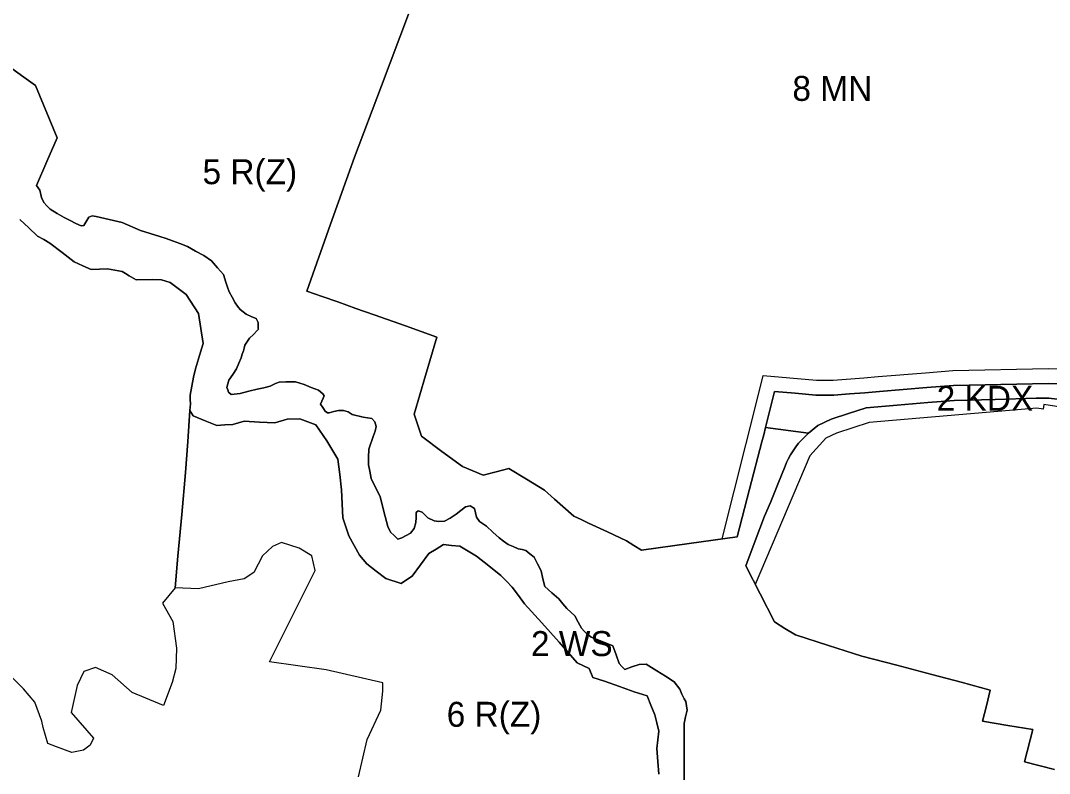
# Model space of a CAD drawing. Extents: x 7423432 to 7425824, y 5537848 to 5539677.
# Drawn here: x 7423877.3 to 7424289.1, y 5538119 to 5538420.5 of the extents above; entities that cross this region are included whole.
import ezdxf

# ---------------------------------------------------------------- set-up
doc = ezdxf.new("R2010")
doc.units = 0
for name, color, linetype in [('linie_rozgraniczajace', 7, 'Continuous'), ('linie_zabudowy_nieprzekraczalne', 7, 'Continuous'), ('oznaczenia_przeznaczen', 7, 'Continuous')]:
    doc.layers.add(name, color=color, linetype=linetype)

msp = doc.modelspace()

# ---------------------------------------------------------------- linework, layer by layer
at = {"layer": 'linie_rozgraniczajace'}
for points in [[(7423991.87, 5538312.06), (7424001.41, 5538338.89), (7424010.95, 5538365.72), (7424021.79, 5538394.37), (7424032.63, 5538423.01)], [(7424032.63, 5538423.01), (7424021.79, 5538394.37), (7424010.95, 5538365.72), (7424001.41, 5538338.89), (7423991.87, 5538312.06), (7423998.06, 5538309.91), (7424004.25, 5538307.77), (7424011.58, 5538305.17), (7424018.92, 5538302.58), (7424031.43, 5538298.16), (7424043.93, 5538293.74), (7424039.42, 5538278.32), (7424034.91, 5538262.9), (7424036.37, 5538258.45), (7424037.83, 5538254), (7424045.99, 5538247.95), (7424054.16, 5538241.89), (7424058.32, 5538240.15), (7424062.47, 5538238.41), (7424067.63, 5538239.74), (7424072.79, 5538241.07), (7424079.89, 5538236.76), (7424086.99, 5538232.44), (7424091.06, 5538228.75), (7424098.73, 5538222), (7424101.67, 5538220.62), (7424104.61, 5538219.24), (7424112.21, 5538215.69), (7424117.33, 5538213.3), (7424119.82, 5538212.14), (7424122.81, 5538210.23), (7424125.8, 5538208.32), (7424144.96, 5538211.02), (7424164.12, 5538213.72), (7424169.09, 5538232.74), (7424174.06, 5538251.75), (7424174.78, 5538254.61), (7424175.5, 5538257.47), (7424192.66, 5538255.29), (7424188.76, 5538251.27), (7424187.65, 5538249.74), (7424186.54, 5538248.2), (7424185.54, 5538246.52), (7424184.53, 5538244.85), (7424183.96, 5538243.44), (7424183.39, 5538242.04), (7424180.43, 5538234.77), (7424177.48, 5538227.5), (7424175.14, 5538221.98), (7424171.36, 5538212.06), (7424167.58, 5538202.15), (7424173.35, 5538190.89), (7424179.12, 5538179.63)], [(7423918.01, 5538339.57), (7423912.81, 5538340.81), (7423907.61, 5538342.06), (7423905.99, 5538342.25), (7423904.7, 5538341.7), (7423902.64, 5538338.35), (7423901.62, 5538338.21), (7423899.49, 5538339.2), (7423897.14, 5538340.37), (7423894.79, 5538341.54), (7423891.97, 5538343.22), (7423889.14, 5538344.9), (7423887.86, 5538346.24), (7423886.58, 5538347.58), (7423885.73, 5538349.58), (7423885.04, 5538352.54), (7423883.72, 5538354.42), (7423887.88, 5538363.99), (7423892.04, 5538373.57), (7423883.3, 5538394.46), (7423878.57, 5538397.86), (7423873.83, 5538401.26)], [(7423873.83, 5538401.26), (7423878.57, 5538397.86), (7423883.3, 5538394.46), (7423892.04, 5538373.57), (7423887.88, 5538363.99), (7423883.72, 5538354.42), (7423885.04, 5538352.54), (7423885.73, 5538349.58), (7423886.58, 5538347.58), (7423887.86, 5538346.24), (7423889.14, 5538344.9), (7423891.97, 5538343.22), (7423894.79, 5538341.54), (7423897.14, 5538340.37), (7423899.49, 5538339.2), (7423901.62, 5538338.21), (7423902.64, 5538338.35), (7423904.7, 5538341.7), (7423905.99, 5538342.25), (7423907.61, 5538342.06), (7423912.81, 5538340.81), (7423918.01, 5538339.57), (7423925.28, 5538336.37), (7423929.15, 5538335.19), (7423933.03, 5538334), (7423935.55, 5538333.16), (7423938.08, 5538332.32), (7423941.1, 5538331.16), (7423944.11, 5538330.01), (7423947.37, 5538328.18), (7423950.62, 5538326.34), (7423953.72, 5538324.24), (7423956.1, 5538321.5)], [(7423877.01, 5538340.77), (7423880.57, 5538337.47), (7423884.12, 5538334.18), (7423886.59, 5538332.76), (7423889.05, 5538331.34), (7423893.91, 5538327.59), (7423898.76, 5538323.85), (7423902.19, 5538322.29), (7423905.61, 5538320.73), (7423908.89, 5538320.86), (7423912.18, 5538321), (7423915.06, 5538320.49), (7423917.95, 5538319.99), (7423919.36, 5538319.11), (7423920.77, 5538318.23), (7423923.57, 5538316.63), (7423930.17, 5538316.75), (7423933.71, 5538316.64), (7423935.47, 5538316.09), (7423937.23, 5538315.55), (7423943.66, 5538310.74), (7423948.48, 5538303.19), (7423949.45, 5538297.19), (7423950.42, 5538291.19), (7423949.36, 5538287.71), (7423947.41, 5538280.97), (7423946.52, 5538277.7), (7423945.84, 5538274.1), (7423945.15, 5538270.5), (7423945.24, 5538268.73), (7423945.33, 5538266.96), (7423945.09, 5538264.34), (7423944.23, 5538251.91), (7423943.37, 5538239.48), (7423941.83, 5538222.72), (7423940.29, 5538205.97), (7423939.14, 5538193.23), (7423934.12, 5538187.13), (7423938.27, 5538179.8), (7423939.74, 5538169.09), (7423939.5, 5538160.93), (7423937.96, 5538155.39), (7423934.56, 5538146.18), (7423921.97, 5538151.34), (7423913.99, 5538158.45), (7423907.31, 5538161.36), (7423902.7, 5538159.77), (7423900.03, 5538154.17), (7423897.53, 5538143.3), (7423906.46, 5538133.01), (7423905.24, 5538130.27), (7423902.52, 5538128.21), (7423897.8, 5538127.29), (7423891.69, 5538129.62), (7423888.29, 5538130.9), (7423886.33, 5538137.3), (7423885.87, 5538139.83), (7423883.03, 5538147.47), (7423878.5, 5538152.86), (7423877.33, 5538153.99), (7423872.44, 5538158.9)], [(7424132.83, 5538118.67), (7424132.43, 5538123.79), (7424132.03, 5538128.9), (7424132.44, 5538132.38), (7424132.85, 5538135.87), (7424132.01, 5538139.16), (7424131.17, 5538142.44), (7424129.64, 5538146.23), (7424128.1, 5538150.01), (7424122.87, 5538151.62), (7424116.99, 5538153.79), (7424111.11, 5538155.95), (7424106.32, 5538157.38), (7424104.96, 5538160.92), (7424100.11, 5538163.28), (7424096.52, 5538167.41), (7424092.93, 5538171.54), (7424086, 5538179.23), (7424079.07, 5538186.92), (7424076.56, 5538190.26), (7424074.04, 5538193.6), (7424071.82, 5538195.89), (7424069.6, 5538198.18), (7424064.71, 5538202.09), (7424059.82, 5538206), (7424056.48, 5538207.96), (7424053.14, 5538209.92), (7424049.87, 5538210.25), (7424046.6, 5538210.58), (7424043.64, 5538208.81), (7424040.68, 5538207.04), (7424037.35, 5538202.48), (7424034.02, 5538197.92), (7424031.82, 5538196.5), (7424029.62, 5538195.08), (7424023.52, 5538197.04), (7424019.71, 5538199.98), (7424015.89, 5538202.92), (7424013.02, 5538206.31), (7424010.86, 5538210.18), (7424008.7, 5538214.05), (7424007.54, 5538217.66), (7424006.38, 5538221.26), (7424006.06, 5538226.91), (7424005.74, 5538232.55), (7424005.06, 5538238.68), (7424004.37, 5538244.8), (7423999.96, 5538252.17), (7423995.48, 5538258.5), (7423989.13, 5538260.92), (7423984.04, 5538260.87), (7423979.09, 5538259.34), (7423972.93, 5538259.69), (7423966.77, 5538260.03), (7423962.31, 5538258.75), (7423959.09, 5538258.5), (7423955.87, 5538258.25), (7423951.17, 5538260.19), (7423946.47, 5538262.12), (7423945.09, 5538264.34), (7423945.33, 5538266.96), (7423945.24, 5538268.73), (7423945.15, 5538270.5), (7423945.84, 5538274.1), (7423946.52, 5538277.7), (7423947.41, 5538280.97), (7423949.36, 5538287.71), (7423950.42, 5538291.19), (7423949.45, 5538297.19), (7423948.48, 5538303.19), (7423943.66, 5538310.74), (7423937.23, 5538315.55), (7423935.47, 5538316.09), (7423933.71, 5538316.64), (7423930.17, 5538316.75), (7423923.57, 5538316.63), (7423920.77, 5538318.23), (7423919.36, 5538319.11), (7423917.95, 5538319.99), (7423915.06, 5538320.49), (7423912.18, 5538321), (7423908.89, 5538320.86), (7423905.61, 5538320.73), (7423902.19, 5538322.29), (7423898.76, 5538323.85), (7423893.91, 5538327.59), (7423889.05, 5538331.34), (7423886.59, 5538332.76), (7423884.12, 5538334.18), (7423880.57, 5538337.47), (7423877.01, 5538340.77)], [(7424044.79, 5538219.83), (7424042.88, 5538220.17), (7424040.3, 5538221.32), (7424038.13, 5538223.55), (7424036.42, 5538224.14), (7424035.68, 5538223.39), (7424035.63, 5538221.42), (7424035.59, 5538219.46), (7424034.84, 5538217.01), (7424033.43, 5538215.13), (7424029.87, 5538213.27), (7424028.28, 5538212.74), (7424026.87, 5538214.18), (7424025.45, 5538215.61), (7424024.27, 5538217.91), (7424022.75, 5538223.89), (7424021.24, 5538229.86), (7424019.41, 5538233.44), (7424017.59, 5538237.03), (7424017.08, 5538240.03), (7424016.65, 5538242.53), (7424016.6, 5538244.03), (7424016.54, 5538245.52), (7424016.74, 5538248.87), (7424017.21, 5538250.41), (7424017.87, 5538252.3), (7424018.44, 5538253.88), (7424019.3, 5538256.08), (7424019.68, 5538257.88), (7424019.18, 5538259.8), (7424017.98, 5538261.11), (7424014.48, 5538261.63), (7424010.09, 5538262.7), (7424008.51, 5538263.71), (7424006.56, 5538264.31), (7424004.58, 5538264.35), (7424002.69, 5538263.84), (7424000.81, 5538263.33), (7424000.12, 5538263.39), (7423999.3, 5538264.09), (7423998.32, 5538265.49), (7423997.35, 5538266.88), (7423998.43, 5538269.28), (7423998.89, 5538270.15), (7423998.31, 5538271.02), (7423996.52, 5538272.39), (7423993.69, 5538273.53), (7423990.87, 5538274.66), (7423987.35, 5538275.83), (7423983.48, 5538275.85), (7423980.86, 5538275.6), (7423979.42, 5538275.13), (7423977.19, 5538274.05), (7423974.75, 5538273.37), (7423972.06, 5538272.91), (7423968.63, 5538272), (7423965.2, 5538271.1), (7423961.58, 5538270.78), (7423960.59, 5538271.69), (7423960.24, 5538272.62), (7423959.89, 5538273.55), (7423960.68, 5538276.45), (7423962.23, 5538278.74), (7423963.78, 5538281.02), (7423964.7, 5538283.23), (7423965.61, 5538285.44), (7423966.06, 5538286.83), (7423966.5, 5538288.23), (7423966.77, 5538289.33), (7423967.04, 5538290.43), (7423968.93, 5538293.24), (7423970.51, 5538294.79), (7423972.09, 5538296.35), (7423972.5, 5538296.88), (7423972.49, 5538297.17), (7423972.47, 5538298.19), (7423972.45, 5538299.51), (7423971.66, 5538301.18), (7423969.9, 5538301.85), (7423967.57, 5538302.95), (7423965.23, 5538304.81), (7423964.19, 5538306.11), (7423963.16, 5538307.4), (7423962, 5538309.63), (7423960.85, 5538311.86), (7423960.17, 5538313.76), (7423959.49, 5538315.65), (7423958.49, 5538318.75), (7423956.1, 5538321.5), (7423953.72, 5538324.24), (7423950.62, 5538326.34), (7423947.37, 5538328.18), (7423944.11, 5538330.01), (7423941.1, 5538331.16), (7423938.08, 5538332.32), (7423935.55, 5538333.16), (7423933.03, 5538334), (7423929.15, 5538335.19), (7423925.28, 5538336.37), (7423918.01, 5538339.57)], [(7423956.1, 5538321.5), (7423958.49, 5538318.75), (7423959.49, 5538315.65), (7423960.17, 5538313.76), (7423960.85, 5538311.86), (7423962, 5538309.63), (7423963.16, 5538307.4), (7423964.19, 5538306.11), (7423965.23, 5538304.81), (7423967.57, 5538302.95), (7423969.9, 5538301.85), (7423971.66, 5538301.18), (7423972.45, 5538299.51), (7423972.47, 5538298.19), (7423972.49, 5538297.17), (7423972.5, 5538296.88), (7423972.09, 5538296.35), (7423970.51, 5538294.79), (7423968.93, 5538293.24), (7423967.04, 5538290.43), (7423966.77, 5538289.33), (7423966.5, 5538288.23), (7423966.06, 5538286.83), (7423965.61, 5538285.44), (7423964.7, 5538283.23), (7423963.78, 5538281.02), (7423962.23, 5538278.74), (7423960.68, 5538276.45), (7423959.89, 5538273.55), (7423960.24, 5538272.62), (7423960.59, 5538271.69), (7423961.58, 5538270.78), (7423965.2, 5538271.1), (7423968.63, 5538272), (7423972.06, 5538272.91), (7423974.75, 5538273.37), (7423977.19, 5538274.05), (7423979.42, 5538275.13), (7423980.86, 5538275.6), (7423983.48, 5538275.85), (7423987.35, 5538275.83), (7423990.87, 5538274.66), (7423993.69, 5538273.53), (7423996.52, 5538272.39), (7423998.31, 5538271.02), (7423998.89, 5538270.15), (7423998.43, 5538269.28), (7423997.35, 5538266.88), (7423998.32, 5538265.49), (7423999.3, 5538264.09), (7424000.12, 5538263.39), (7424000.81, 5538263.33), (7424002.69, 5538263.84), (7424004.58, 5538264.35), (7424006.56, 5538264.31), (7424008.51, 5538263.71), (7424010.09, 5538262.7), (7424014.48, 5538261.63), (7424017.98, 5538261.11), (7424019.18, 5538259.8), (7424019.68, 5538257.88), (7424019.3, 5538256.08), (7424018.44, 5538253.88), (7424017.87, 5538252.3), (7424017.21, 5538250.41), (7424016.74, 5538248.87), (7424016.54, 5538245.52), (7424016.6, 5538244.03), (7424016.65, 5538242.53), (7424017.08, 5538240.03), (7424017.59, 5538237.03), (7424019.41, 5538233.44), (7424021.24, 5538229.86), (7424022.75, 5538223.89), (7424024.27, 5538217.91), (7424025.45, 5538215.61), (7424026.87, 5538214.18), (7424028.28, 5538212.74), (7424029.87, 5538213.27), (7424033.43, 5538215.13), (7424034.84, 5538217.01), (7424035.59, 5538219.46), (7424035.63, 5538221.42), (7424035.68, 5538223.39), (7424036.42, 5538224.14), (7424038.13, 5538223.55), (7424040.3, 5538221.32), (7424042.88, 5538220.17), (7424044.79, 5538219.83), (7424046.95, 5538219.92), (7424049.21, 5538221.2), (7424051.64, 5538222.84), (7424053.49, 5538224.26), (7424055.37, 5538225.69), (7424057.23, 5538226.16), (7424059.03, 5538225.04), (7424059.44, 5538223.29), (7424059.86, 5538221.53), (7424060.98, 5538219.82), (7424063.76, 5538217.94)], [(7424296.11, 5538274.99), (7424288.7, 5538275.17), (7424269.7, 5538274.72), (7424250.71, 5538274.27), (7424245.36, 5538273.87), (7424240.02, 5538273.46), (7424230.55, 5538272.68), (7424221.08, 5538271.9), (7424218.18, 5538271.65), (7424215.28, 5538271.41), (7424209.05, 5538270.94), (7424202.82, 5538270.47), (7424199.22, 5538270.49), (7424195.61, 5538270.51), (7424187.37, 5538271.2), (7424179.13, 5538271.9), (7424175.5, 5538257.47), (7424174.78, 5538254.61), (7424174.06, 5538251.75), (7424169.09, 5538232.74), (7424164.12, 5538213.72), (7424144.96, 5538211.02), (7424125.8, 5538208.32), (7424122.81, 5538210.23), (7424119.82, 5538212.14), (7424117.33, 5538213.3), (7424112.21, 5538215.69), (7424104.61, 5538219.24), (7424101.67, 5538220.62), (7424098.73, 5538222), (7424091.06, 5538228.75), (7424086.99, 5538232.44), (7424079.89, 5538236.76), (7424072.79, 5538241.07), (7424067.63, 5538239.74), (7424062.47, 5538238.41), (7424058.32, 5538240.15), (7424054.16, 5538241.89), (7424045.99, 5538247.95), (7424037.83, 5538254), (7424036.37, 5538258.45), (7424034.91, 5538262.9), (7424039.42, 5538278.32), (7424043.93, 5538293.74), (7424031.43, 5538298.16), (7424018.92, 5538302.58), (7424011.58, 5538305.17), (7424004.25, 5538307.77), (7423998.06, 5538309.91), (7423991.87, 5538312.06)], [(7424296.63, 5538268.28), (7424288.93, 5538269.22), (7424286.37, 5538269.23), (7424283.82, 5538269.23), (7424267.42, 5538268.76), (7424251.02, 5538268.28), (7424245.76, 5538267.88), (7424240.49, 5538267.47), (7424228.14, 5538266.45), (7424215.78, 5538265.43), (7424208.75, 5538263.13), (7424201.72, 5538260.84), (7424196.4, 5538258.31), (7424192.66, 5538255.29), (7424175.5, 5538257.47), (7424179.13, 5538271.9), (7424187.37, 5538271.2), (7424195.61, 5538270.51), (7424199.22, 5538270.49), (7424202.82, 5538270.47), (7424209.05, 5538270.94), (7424215.28, 5538271.41), (7424218.18, 5538271.65), (7424221.08, 5538271.9), (7424230.55, 5538272.68), (7424240.02, 5538273.46), (7424245.36, 5538273.87), (7424250.71, 5538274.27), (7424269.7, 5538274.72), (7424288.7, 5538275.17), (7424296.11, 5538274.99)], [(7424167.58, 5538202.15), (7424171.36, 5538212.06), (7424175.14, 5538221.98), (7424177.48, 5538227.5), (7424180.43, 5538234.77), (7424183.39, 5538242.04), (7424183.96, 5538243.44), (7424184.53, 5538244.85), (7424185.54, 5538246.52), (7424186.54, 5538248.2), (7424187.65, 5538249.74), (7424188.76, 5538251.27), (7424192.66, 5538255.29), (7424196.4, 5538258.31), (7424201.72, 5538260.84), (7424208.75, 5538263.13), (7424215.78, 5538265.43), (7424228.14, 5538266.45), (7424240.49, 5538267.47), (7424245.76, 5538267.88), (7424251.02, 5538268.28), (7424267.42, 5538268.76), (7424283.82, 5538269.23), (7424286.37, 5538269.23), (7424288.93, 5538269.22), (7424296.63, 5538268.28)], [(7423939.14, 5538193.23), (7423940.29, 5538205.97), (7423941.83, 5538222.72), (7423943.37, 5538239.48), (7423944.23, 5538251.91), (7423945.09, 5538264.34), (7423946.47, 5538262.12), (7423951.17, 5538260.19), (7423955.87, 5538258.25), (7423959.09, 5538258.5), (7423962.31, 5538258.75), (7423966.77, 5538260.03), (7423972.93, 5538259.69), (7423979.09, 5538259.34), (7423984.04, 5538260.87), (7423989.13, 5538260.92), (7423995.48, 5538258.5), (7423999.96, 5538252.17), (7424004.37, 5538244.8), (7424005.06, 5538238.68), (7424005.74, 5538232.55), (7424006.06, 5538226.91), (7424006.38, 5538221.26), (7424007.54, 5538217.66), (7424008.7, 5538214.05), (7424010.86, 5538210.18), (7424013.02, 5538206.31), (7424015.89, 5538202.92), (7424019.71, 5538199.98), (7424023.52, 5538197.04), (7424029.62, 5538195.08), (7424031.82, 5538196.5), (7424034.02, 5538197.92), (7424037.35, 5538202.48), (7424040.68, 5538207.04), (7424043.64, 5538208.81), (7424046.6, 5538210.58), (7424049.87, 5538210.25), (7424053.14, 5538209.92), (7424056.48, 5538207.96), (7424059.82, 5538206), (7424064.71, 5538202.09), (7424069.6, 5538198.18), (7424071.82, 5538195.89), (7424074.04, 5538193.6), (7424076.56, 5538190.26), (7424079.07, 5538186.92), (7424086, 5538179.23), (7424092.93, 5538171.54), (7424096.52, 5538167.41), (7424100.11, 5538163.28), (7424104.96, 5538160.92), (7424106.32, 5538157.38), (7424111.11, 5538155.95), (7424116.99, 5538153.79), (7424122.87, 5538151.62), (7424128.1, 5538150.01), (7424129.64, 5538146.23), (7424131.17, 5538142.44), (7424132.01, 5538139.16), (7424132.85, 5538135.87), (7424132.44, 5538132.38), (7424132.03, 5538128.9), (7424132.43, 5538123.79), (7424132.83, 5538118.67)], [(7424142.93, 5538116.41), (7424142.91, 5538127.67), (7424142.88, 5538138.93), (7424143.48, 5538141.62), (7424144.08, 5538144.31), (7424143.81, 5538146.03), (7424143.55, 5538147.76), (7424142.87, 5538148.81), (7424142.02, 5538150.75), (7424141.17, 5538152.68), (7424138.88, 5538155.68), (7424135.45, 5538157.84), (7424132.02, 5538159.99), (7424129.9, 5538161.33), (7424127.78, 5538162.66), (7424124.89, 5538162.61), (7424122, 5538161.61), (7424119.12, 5538160.61), (7424118, 5538161.79), (7424116.89, 5538162.97), (7424115.67, 5538166.49), (7424114.44, 5538170.01), (7424110.1, 5538171.75), (7424105.76, 5538173.49), (7424104.87, 5538174.14), (7424103.98, 5538174.8), (7424102.94, 5538175.95), (7424101.89, 5538177.11), (7424100.51, 5538179.6), (7424099.12, 5538182.08), (7424097.52, 5538183.54), (7424095.92, 5538184.99), (7424094.34, 5538186.91), (7424092.75, 5538188.84), (7424089.96, 5538191.33), (7424087.16, 5538193.83), (7424086.42, 5538196.95), (7424085.67, 5538200.08), (7424084.27, 5538202.83), (7424082.87, 5538205.58), (7424081.2, 5538206.94), (7424079.53, 5538208.29), (7424078.04, 5538208.59), (7424076.54, 5538208.9), (7424074.5, 5538209.8), (7424072.45, 5538210.69), (7424070.64, 5538211.98), (7424068.83, 5538213.26), (7424066.29, 5538215.6), (7424063.76, 5538217.94), (7424060.98, 5538219.82), (7424059.86, 5538221.53), (7424059.44, 5538223.29), (7424059.03, 5538225.04), (7424057.23, 5538226.16), (7424055.37, 5538225.69), (7424053.49, 5538224.26), (7424051.64, 5538222.84), (7424049.21, 5538221.2), (7424046.95, 5538219.92), (7424044.79, 5538219.83)], [(7424063.76, 5538217.94), (7424066.29, 5538215.6), (7424068.83, 5538213.26), (7424070.64, 5538211.98), (7424072.45, 5538210.69), (7424074.5, 5538209.8), (7424076.54, 5538208.9), (7424078.04, 5538208.59), (7424079.53, 5538208.29), (7424081.2, 5538206.94), (7424082.87, 5538205.58), (7424084.27, 5538202.83), (7424085.67, 5538200.08), (7424086.42, 5538196.95), (7424087.16, 5538193.83), (7424089.96, 5538191.33), (7424092.75, 5538188.84), (7424094.34, 5538186.91), (7424095.92, 5538184.99), (7424097.52, 5538183.54), (7424099.12, 5538182.08), (7424100.51, 5538179.6), (7424101.89, 5538177.11), (7424102.94, 5538175.95), (7424103.98, 5538174.8), (7424104.87, 5538174.14), (7424105.76, 5538173.49), (7424110.1, 5538171.75), (7424114.44, 5538170.01), (7424115.67, 5538166.49), (7424116.89, 5538162.97), (7424118, 5538161.79), (7424119.12, 5538160.61), (7424122, 5538161.61), (7424124.89, 5538162.61), (7424127.78, 5538162.66), (7424129.9, 5538161.33), (7424132.02, 5538159.99), (7424135.45, 5538157.84), (7424138.88, 5538155.68), (7424141.17, 5538152.68), (7424142.02, 5538150.75), (7424142.87, 5538148.81), (7424143.55, 5538147.76), (7424143.81, 5538146.03), (7424144.08, 5538144.31), (7424143.48, 5538141.62), (7424142.88, 5538138.93), (7424142.91, 5538127.67), (7424142.93, 5538116.41)], [(7424012.61, 5538117.65), (7424016.04, 5538132.48), (7424021.57, 5538144.34), (7424022.33, 5538151.91), (7424022.33, 5538155.19), (7423999.65, 5538160.4), (7423976.97, 5538163.65), (7423995.21, 5538200.25), (7423993.88, 5538206.16), (7423988.8, 5538209.2), (7423981.76, 5538211.38), (7423978.11, 5538209.89), (7423974.21, 5538206.14), (7423970.7, 5538199.43), (7423966.76, 5538196.95), (7423960.45, 5538195.66), (7423948.59, 5538192.88), (7423939.14, 5538193.23)], [(7424291.16, 5538120.58), (7424279.12, 5538123.64), (7424282.51, 5538136.57), (7424272.42, 5538138.21), (7424262.33, 5538139.85), (7424263.89, 5538146.09), (7424265.46, 5538152.33), (7424253.75, 5538155.46), (7424242.04, 5538158.58), (7424228.05, 5538162.28), (7424214.06, 5538165.97), (7424200.76, 5538170.22), (7424187.47, 5538174.47), (7424183.29, 5538177.05), (7424179.12, 5538179.63), (7424173.35, 5538190.89), (7424167.58, 5538202.15)], [(7424179.12, 5538179.63), (7424183.29, 5538177.05), (7424187.47, 5538174.47), (7424200.76, 5538170.22), (7424214.06, 5538165.97), (7424228.05, 5538162.28), (7424242.04, 5538158.58), (7424253.75, 5538155.46), (7424265.46, 5538152.33), (7424263.89, 5538146.09), (7424262.33, 5538139.85), (7424272.42, 5538138.21), (7424282.51, 5538136.57), (7424279.12, 5538123.64), (7424291.16, 5538120.58)]]:
    msp.add_lwpolyline(points, dxfattribs=at)
at = {"layer": 'linie_zabudowy_nieprzekraczalne'}
for points in [[(7424158.13, 5538212.88), (7424172.38, 5538269.69), (7424174.56, 5538278.3), (7424195.88, 5538276.5), (7424202.61, 5538276.47), (7424214.81, 5538277.39), (7424220.58, 5538277.88), (7424239.54, 5538279.44), (7424250.41, 5538280.27), (7424288.71, 5538281.18), (7424303.64, 5538280.8)], [(7424309.1, 5538263.27), (7424286.91, 5538266.75), (7424286.63, 5538264.9), (7424284.05, 5538265.29), (7424216.97, 5538259.51), (7424203.95, 5538255.25), (7424199.62, 5538253.19), (7424193.24, 5538246.2), (7424171.41, 5538194.68)]]:
    msp.add_lwpolyline(points, dxfattribs=at)

# ---------------------------------------------------------------- texts
at = {"layer": 'oznaczenia_przeznaczen'}
for s, p in [('8 MN', (7424186.26, 5538388.31)), ('5 R(Z)', (7423950.15, 5538354.95)), ('2 KDX', (7424244, 5538264.2)), ('2 WS', (7424081.62, 5538165.95)), ('6 R(Z)', (7424047.89, 5538137.63))]:
    msp.add_text(s, height=10, dxfattribs=at).set_placement(p)

doc.saveas('drawing.dxf')
